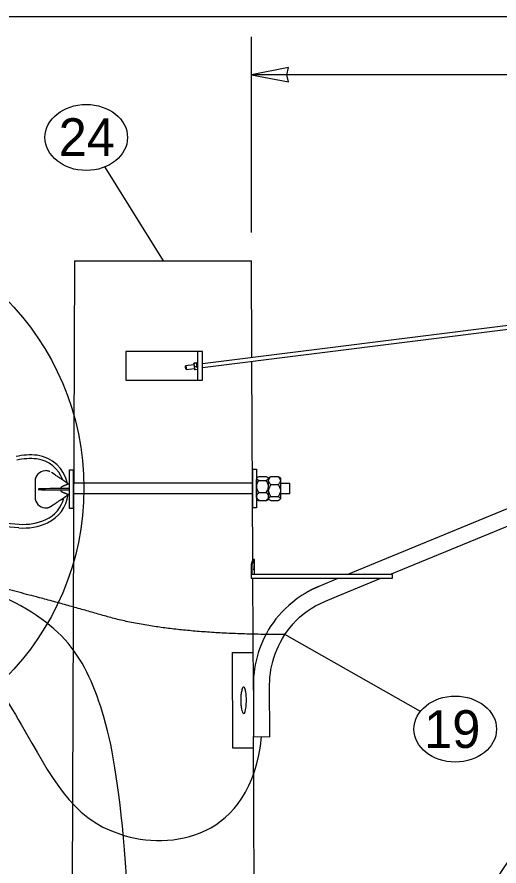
# Model space of a CAD drawing. Extents: x 99862 to 104211, y 98939 to 102076.
# Drawn here: x 100127 to 100331.4, y 101715.8 to 102075.5 of the extents above; entities that cross this region are included whole.
import ezdxf

# ---------------------------------------------------------------- set-up
doc = ezdxf.new("R2010")
doc.units = 0
for name, color, linetype in [('Level 1', 7, 'Continuous'), ('Level 12', 7, 'Continuous'), ('Level 15', 7, 'Continuous'), ('Level 18', 7, 'Continuous'), ('Level 20', 7, 'Continuous'), ('Level 32', 7, 'Continuous'), ('Level 33', 7, 'Continuous'), ('Level 34', 7, 'Continuous'), ('Level 38', 7, 'Continuous'), ('Level 40', 7, 'Continuous'), ('Level 49', 7, 'Continuous'), ('Level 7', 7, 'Continuous')]:
    doc.layers.add(name, color=color, linetype=linetype)

msp = doc.modelspace()

# ---------------------------------------------------------------- linework, layer by layer
at = {"layer": 'Level 1'}
for p, q in [((100151.45, 101972.17), (100149.21, 101433.5)), ((100151.45, 101972.17), (100226.45, 101972.17)), ((100226.62, 101931.09), (100226.45, 101972.17)), ((100226.98, 101845.43), (100226.63, 101929.52)), ((100227.23, 101790.32), (100227.01, 101837.68)), ((100228.7, 101433.5), (100227.29, 101770.61))]:
    msp.add_line(p, q, dxfattribs=at)
msp.add_lwpolyline([(99862, 99999.5), (103151, 99999.5), (103151, 102075.5), (99862, 102075.5)], close=True, dxfattribs=at)
at = {"layer": 'Level 12'}
for points, degree in [([(100176.93, 101638.26), (100173.89, 101734.54), (100164.15, 101799.98), (100138.47, 101825.12), (100098.36, 101838.8)], 3), ([(100240.57, 101813.83), (100191.29, 101813.83), (100136.84, 101829.72), (100099.22, 101838.98)], 2), ([(100072.35, 101826.16), (100099.14, 101823.34), (100133.1, 101771.89), (100157.98, 101718.14), (100226.04, 101726.6), (100230.75, 101770.54)], 3)]:
    msp.add_open_spline(points, degree=degree, dxfattribs=at)
at = {"layer": 'Level 15'}
for p, q in [((100226.45, 101984.17), (100226.45, 102067.04)), ((100473.47, 102051.04), (100226.45, 102051.04)), ((100164.2, 102011.93), (100188.95, 101972.17)), ((100078.2, 101864.74), (100127.92, 101860.61)), ((100127.79, 101859.05), (100078.07, 101863.19)), ((100298.04, 101781.29), (100240.57, 101813.83))]:
    msp.add_line(p, q, dxfattribs=at)
msp.add_lwpolyline([(100226.45, 102051.04), (100242.18, 102047.96), (100241.45, 102051.04), (100242.18, 102054.13)], close=True, dxfattribs=at)
for centre, radius in [((100041.37, 101875.87), 113.99), ((100504.52, 101599.96), 206.11)]:
    msp.add_circle(centre, radius, dxfattribs=at)
for centre, radius, start, end in [((100132.58, 101865.55), 24.41, 83.055, 104.0887), ((100133.71, 101874.86), 15.04, 11.5094, 83.055), ((100132.58, 101865.55), 22.85, 83.055, 104.0887), ((100133.71, 101874.86), 13.48, 19.3591, 83.055), ((100133.71, 101874.86), 13.48, 294.5861, 346.7651), ((100133.71, 101874.86), 15.04, 294.5861, 353.4239), ((100129.81, 101883.38), 24.41, 265.2438, 294.5861), ((100129.81, 101883.38), 22.85, 265.2438, 294.5861)]:
    msp.add_arc(centre, radius, start, end, dxfattribs=at)
at = {"layer": 'Level 18'}
for p, q in [((100238.71, 101877.94), (100242.66, 101877.94)), ((100242.66, 101873.48), (100242.66, 101877.94)), ((100242.66, 101873.48), (100238.71, 101873.48))]:
    msp.add_line(p, q, dxfattribs=at)
at = {"layer": 'Level 20'}
for centre in [(100156.39, 102024.46), (100312.82, 101773.79)]:
    msp.add_ellipse(centre, major_axis=(-17.5, 0), ratio=0.8, dxfattribs=at)
at = {"layer": 'Level 32'}
for p, q in [((100266.99, 101839.23), (100578.4, 101967.79)), ((100285.11, 101839.23), (100583.62, 101962.46)), ((100255.13, 101834.34), (100263.2, 101837.67)), ((100261.55, 101829.51), (100281.33, 101837.67)), ((100257.77, 101827.95), (100261.55, 101829.51)), ((100227.23, 101792.5), (100227.24, 101787.89)), ((100234.21, 101770.48), (100234.14, 101792.52)), ((100227.29, 101770.61), (100234.21, 101770.48))]:
    msp.add_line(p, q, dxfattribs=at)
for points, degree in [([(100247.91, 101830.55), (100250.2, 101832.03), (100252.62, 101833.3), (100255.13, 101834.34)], 2), ([(100247.91, 101830.55), (100242.1, 101826.49), (100235.01, 101819.39), (100228.59, 101806.26), (100227.21, 101797.05), (100227.23, 101792.5)], 3), ([(100234.14, 101792.52), (100234.13, 101796.93), (100235.63, 101805.62), (100243.1, 101818.94), (100251.89, 101825.52), (100257.77, 101827.95)], 3), ([(100227.24, 101787.93), (100227.24, 101787.38), (100227.24, 101786.84), (100227.25, 101786.29), (100227.25, 101784), (100227.26, 101781.71), (100227.29, 101770.61)], 3)]:
    msp.add_open_spline(points, degree=degree, dxfattribs=at)
at = {"layer": 'Level 33'}
for p, q in [((100227.71, 101845.6), (100227.02, 101845.6)), ((100227.72, 101839.23), (100227.72, 101845.58)), ((100226.79, 101839.23), (100226.79, 101843.54)), ((100276.86, 101839.23), (100226.79, 101839.23)), ((100286.23, 101839.23), (100276.97, 101839.23)), ((100277.12, 101839.23), (100277.23, 101839.23)), ((100286.23, 101837.67), (100286.23, 101839.23)), ((100226.32, 101837.67), (100276.86, 101837.67)), ((100276.97, 101837.67), (100286.23, 101837.67)), ((100277.12, 101837.67), (100277.23, 101837.67))]:
    msp.add_line(p, q, dxfattribs=at)
msp.add_ellipse((99942.52, 101829.47), major_axis=(-581.56, 0), ratio=0.027734, start_param=4.201666, end_param=4.202627, dxfattribs=at)
for points, degree in [([(100226.98, 101845.57), (100227, 101845.59), (100227.01, 101845.6), (100227.04, 101845.6), (100227.03, 101845.55), (100226.96, 101845.37), (100226.9, 101845.24), (100226.76, 101844.95), (100226.7, 101844.81), (100226.63, 101844.66)], 3), ([(100226.79, 101843.54), (100227.1, 101844.2), (100227.35, 101844.72), (100227.59, 101845.24), (100227.65, 101845.37), (100227.72, 101845.55), (100227.73, 101845.6), (100227.71, 101845.6)], 3), ([(100226.63, 101844.66), (100226.53, 101844.36), (100226.42, 101843.99), (100226.3, 101843.55)], 2), ([(100226.3, 101843.55), (100226.31, 101841.59), (100226.31, 101839.63), (100226.32, 101837.67)], 2), ([(100227.57, 101841.81), (100227.57, 101841.79), (100227.58, 101841.76), (100227.58, 101841.72), (100227.58, 101841.69), (100227.58, 101841.65), (100227.58, 101841.61), (100227.59, 101841.57), (100227.59, 101841.52), (100227.59, 101841.48), (100227.59, 101841.43), (100227.59, 101841.39), (100227.58, 101841.35), (100227.58, 101841.3), (100227.58, 101841.27), (100227.58, 101841.23), (100227.58, 101841.2), (100227.57, 101841.17), (100227.57, 101841.14), (100227.56, 101841.12), (100227.56, 101841.1), (100227.55, 101841.09), (100227.55, 101841.08), (100227.55, 101841.08), (100227.54, 101841.08), (100227.54, 101841.09), (100227.53, 101841.1), (100227.53, 101841.12), (100227.52, 101841.14), (100227.52, 101841.17), (100227.51, 101841.2), (100227.51, 101841.23), (100227.51, 101841.27), (100227.5, 101841.31), (100227.5, 101841.35), (100227.5, 101841.39), (100227.5, 101841.44), (100227.5, 101841.48), (100227.5, 101841.52), (100227.5, 101841.57), (100227.5, 101841.61), (100227.5, 101841.65), (100227.51, 101841.69), (100227.51, 101841.73), (100227.51, 101841.76), (100227.52, 101841.79), (100227.52, 101841.8), (100227.52, 101841.8), (100227.52, 101841.81)], 3), ([(100227.52, 101843.02), (100227.52, 101843.04), (100227.52, 101843.07), (100227.52, 101843.09), (100227.52, 101843.11), (100227.52, 101843.13), (100227.53, 101843.15), (100227.53, 101843.17), (100227.53, 101843.18), (100227.53, 101843.2), (100227.53, 101843.21), (100227.54, 101843.22), (100227.54, 101843.22), (100227.54, 101843.23), (100227.55, 101843.23), (100227.55, 101843.23), (100227.55, 101843.23), (100227.55, 101843.22), (100227.56, 101843.21), (100227.56, 101843.2), (100227.56, 101843.18), (100227.56, 101843.17), (100227.56, 101843.15), (100227.56, 101843.13), (100227.57, 101843.11), (100227.57, 101843.09), (100227.57, 101843.06), (100227.57, 101843.04), (100227.57, 101843.03), (100227.57, 101843.03), (100227.57, 101843.02)], 3), ([(100227.52, 101841.81), (100227.52, 101841.91), (100227.52, 101842.01), (100227.52, 101842.11), (100227.52, 101842.42), (100227.52, 101842.72), (100227.52, 101843.02)], 3), ([(100227.57, 101843.02), (100227.57, 101842.72), (100227.57, 101842.42), (100227.57, 101842.11), (100227.57, 101842.01), (100227.57, 101841.91), (100227.57, 101841.81)], 3)]:
    msp.add_open_spline(points, degree=degree, dxfattribs=at)
at = {"layer": 'Level 34'}
for p, q in [((100203.62, 101933.77), (100173.1, 101933.77)), ((100173.1, 101933.77), (100173.1, 101921.56)), ((100203.62, 101933.77), (100203.62, 101921.56)), ((100205.65, 101933.77), (100203.62, 101933.77)), ((100205.65, 101921.56), (100205.65, 101933.77)), ((100173.1, 101921.56), (100203.62, 101921.56)), ((100203.62, 101921.56), (100205.65, 101921.56))]:
    msp.add_line(p, q, dxfattribs=at)
at = {"layer": 'Level 38'}
for p, q in [((100134.71, 101878.79), (100134.7, 101872.04)), ((100226.91, 101877.94), (100150.88, 101877.94)), ((100242.66, 101877.94), (100242.66, 101877.94)), ((100146.94, 101875.67), (100141.08, 101875.68)), ((100141.08, 101875.14), (100146.94, 101875.15)), ((100149.27, 101875.7), (100147.8, 101875.7)), ((100147.8, 101875.13), (100149.27, 101875.13)), ((100148.81, 101877.56), (100148.81, 101877.56)), ((100148.81, 101873.26), (100148.81, 101873.26)), ((100226.91, 101873.48), (100150.88, 101873.48))]:
    msp.add_line(p, q, dxfattribs=at)
for centre, start, end in [((100139.21, 101878.79), 94.053, 179.9934), ((100139.2, 101872.04), 179.9934, 265.9339)]:
    msp.add_arc(centre, 4.5, start, end, dxfattribs=at)
for centre, start_param, end_param in [((100143.01, 101875.46), 4.989541, 6.265171), ((100143.01, 101875.36), 0.018014, 1.293644)]:
    msp.add_ellipse(centre, major_axis=(-7.03, 0), ratio=0.031999, start_param=start_param, end_param=end_param, dxfattribs=at)
for points, degree in [([(100141.01, 101882.85), (100140.68, 101883.01), (100140.32, 101883.13), (100139.61, 101883.28), (100139.25, 101883.3), (100138.89, 101883.28)], 3), ([(100146.74, 101879.11), (100146.12, 101879.53), (100145.49, 101879.94), (100144.87, 101880.35), (100143.78, 101881.07), (100142.7, 101881.79), (100141.61, 101882.5)], 3), ([(100148.81, 101877.56), (100148.15, 101878.11), (100147.46, 101878.64), (100146.74, 101879.11)], 2), ([(100146.3, 101876.57), (100146.12, 101876.49), (100145.96, 101876.4), (100145.75, 101876.28), (100145.69, 101876.24), (100145.62, 101876.15), (100145.61, 101876.12), (100145.63, 101876.1)], 3), ([(100145.63, 101874.73), (100145.61, 101874.71), (100145.62, 101874.67), (100145.69, 101874.59), (100145.76, 101874.55), (100145.96, 101874.42), (100146.12, 101874.34), (100146.3, 101874.26)], 3), ([(100147.93, 101877.27), (100147.4, 101877.03), (100146.83, 101876.81), (100146.3, 101876.57)], 2), ([(100146.3, 101874.26), (100146.83, 101874.01), (100147.4, 101873.79), (100147.93, 101873.56)], 2), ([(100147.8, 101875.7), (100147.65, 101875.7), (100147.51, 101875.69), (100147.37, 101875.69), (100147.24, 101875.69), (100147.11, 101875.68), (100146.98, 101875.67), (100146.97, 101875.67), (100146.96, 101875.67), (100146.94, 101875.67)], 3), ([(100146.94, 101875.15), (100146.96, 101875.15), (100146.97, 101875.15), (100146.98, 101875.15), (100147.13, 101875.14), (100147.27, 101875.14), (100147.41, 101875.13), (100147.54, 101875.13), (100147.67, 101875.13), (100147.8, 101875.13)], 3), ([(100148.81, 101877.56), (100148.53, 101877.49), (100148.22, 101877.4), (100147.93, 101877.27)], 2), ([(100149.27, 101877.58), (100149.12, 101877.57), (100148.96, 101877.57), (100148.81, 101877.56)], 2), ([(100141.61, 101868.32), (100142.24, 101868.73), (100142.86, 101869.15), (100143.49, 101869.56), (100144.55, 101870.26), (100145.61, 101870.96), (100146.67, 101871.66), (100146.69, 101871.68), (100146.72, 101871.69), (100146.74, 101871.71)], 3), ([(100146.74, 101871.71), (100147.46, 101872.19), (100148.14, 101872.71), (100148.81, 101873.26)], 2), ([(100147.93, 101873.56), (100148.22, 101873.43), (100148.53, 101873.33), (100148.81, 101873.26)], 2), ([(100148.81, 101873.26), (100148.96, 101873.26), (100149.12, 101873.25), (100149.27, 101873.25)], 2), ([(100138.89, 101867.55), (100139.61, 101867.5), (100140.34, 101867.65), (100141, 101867.98)], 2), ([(100141, 101867.98), (100141.21, 101868.08), (100141.41, 101868.19), (100141.61, 101868.32)], 2)]:
    msp.add_open_spline(points, degree=degree, dxfattribs=at)
at = {"layer": 'Level 40'}
for p, q in [((100228.6, 101876.87), (100228.6, 101879.51)), ((100229.63, 101880.79), (100232.62, 101880.79)), ((100229.63, 101879.15), (100232.62, 101879.15)), ((100233.3, 101880.44), (100233.3, 101880.44)), ((100233.65, 101879.88), (100233.65, 101880.05)), ((100233.65, 101876.87), (100233.65, 101879.88)), ((100233.65, 101876.87), (100233.65, 101879.51)), ((100234.01, 101880.44), (100233.74, 101880.26)), ((100234.68, 101880.79), (100237.68, 101880.79)), ((100238.71, 101880.21), (100238.35, 101880.45)), ((100238.71, 101880.21), (100238.71, 101879.25)), ((100238.71, 101879.25), (100238.71, 101878.89)), ((100238.71, 101878.89), (100238.71, 101875.07)), ((100228.6, 101876.35), (100228.6, 101876.87)), ((100228.6, 101871.91), (100228.6, 101876.35)), ((100229.63, 101874.07), (100232.62, 101874.07)), ((100233.65, 101876.35), (100233.65, 101876.87)), ((100233.65, 101876.35), (100233.65, 101876.87)), ((100233.65, 101872.52), (100233.65, 101876.35)), ((100233.65, 101872.52), (100233.65, 101876.35)), ((100234.68, 101877.35), (100237.68, 101877.35)), ((100238.71, 101875.07), (100238.71, 101874.55)), ((100238.71, 101874.55), (100238.71, 101871.53)), ((100228.6, 101872.17), (100228.6, 101872.52)), ((100228.95, 101870.97), (100228.68, 101871.15)), ((100229.63, 101870.63), (100232.62, 101870.63)), ((100233.65, 101871.21), (100233.3, 101870.97)), ((100233.65, 101872.17), (100233.65, 101872.52)), ((100233.65, 101872.17), (100233.65, 101872.52)), ((100233.65, 101871.21), (100233.65, 101872.17)), ((100233.65, 101871.91), (100233.65, 101872.17)), ((100234.68, 101872.27), (100237.68, 101872.27)), ((100234.68, 101870.63), (100237.68, 101870.63)), ((100238.35, 101870.97), (100238.35, 101870.97)), ((100238.71, 101871.53), (100238.71, 101871.36))]:
    msp.add_line(p, q, dxfattribs=at)
for points in [[(100149.26, 101883.57), (100150.88, 101883.57), (100150.88, 101867.21), (100149.26, 101867.21)], [(100226.97, 101883.89), (100228.59, 101883.89), (100228.59, 101867.53), (100226.97, 101867.53)]]:
    msp.add_lwpolyline(points, close=True, dxfattribs=at)
for points, degree in [([(100228.63, 101879.81), (100228.62, 101879.72), (100228.61, 101879.62), (100228.6, 101879.51)], 2), ([(100228.6, 101876.87), (100228.64, 101877.29), (100228.77, 101877.7), (100229.14, 101878.46), (100229.38, 101878.81), (100229.63, 101879.15)], 3), ([(100228.63, 101879.81), (100228.65, 101879.94), (100228.67, 101880.07), (100228.67, 101880.2)], 3), ([(100229.63, 101879.15), (100229.37, 101879.26), (100229.14, 101879.37), (100228.81, 101879.59), (100228.69, 101879.7), (100228.63, 101879.81)], 3), ([(100228.67, 101880.2), (100228.74, 101880.28), (100228.83, 101880.36), (100229.14, 101880.57), (100229.37, 101880.68), (100229.63, 101880.79)], 3), ([(100232.62, 101880.79), (100232.88, 101880.68), (100233.12, 101880.57), (100233.48, 101880.32), (100233.62, 101880.19), (100233.65, 101880.05)], 3), ([(100233.65, 101879.88), (100233.62, 101879.75), (100233.49, 101879.62), (100233.12, 101879.37), (100232.88, 101879.26), (100232.62, 101879.15)], 3), ([(100233.65, 101876.87), (100233.62, 101877.29), (100233.48, 101877.7), (100233.12, 101878.46), (100232.88, 101878.81), (100232.62, 101879.15)], 3), ([(100234.68, 101880.79), (100234.43, 101880.56), (100234.19, 101880.32), (100233.82, 101879.81), (100233.69, 101879.53), (100233.65, 101879.25)], 3), ([(100233.65, 101879.51), (100233.68, 101879.73), (100233.7, 101879.91), (100233.71, 101880.04), (100233.73, 101880.19), (100233.74, 101880.26), (100233.74, 101880.26)], 3), ([(100233.65, 101878.89), (100233.69, 101878.61), (100233.82, 101878.34), (100234.19, 101877.82), (100234.43, 101877.58), (100234.68, 101877.35)], 3), ([(100234.01, 101880.44), (100234.19, 101880.57), (100234.43, 101880.68), (100234.68, 101880.79)], 2), ([(100237.68, 101880.79), (100237.94, 101880.68), (100238.17, 101880.57), (100238.35, 101880.44)], 2), ([(100238.71, 101879.25), (100238.67, 101879.53), (100238.54, 101879.81), (100238.17, 101880.32), (100237.94, 101880.56), (100237.68, 101880.79)], 3), ([(100237.68, 101877.35), (100237.94, 101877.58), (100238.17, 101877.82), (100238.54, 101878.33), (100238.67, 101878.61), (100238.71, 101878.89)], 3), ([(100229.63, 101874.07), (100229.37, 101874.4), (100229.14, 101874.76), (100228.77, 101875.52), (100228.64, 101875.92), (100228.6, 101876.35)], 3), ([(100228.6, 101872.52), (100228.64, 101872.81), (100228.77, 101873.08), (100229.14, 101873.6), (100229.37, 101873.84), (100229.63, 101874.07)], 3), ([(100232.62, 101874.07), (100232.88, 101874.4), (100233.12, 101874.76), (100233.48, 101875.52), (100233.62, 101875.92), (100233.65, 101876.35)], 3), ([(100232.62, 101874.07), (100232.88, 101873.84), (100233.12, 101873.6), (100233.48, 101873.08), (100233.62, 101872.81), (100233.65, 101872.52)], 3), ([(100234.68, 101877.35), (100234.43, 101877.02), (100234.19, 101876.66), (100233.82, 101875.9), (100233.69, 101875.49), (100233.65, 101875.07)], 3), ([(100233.65, 101874.55), (100233.69, 101874.13), (100233.82, 101873.72), (100234.19, 101872.96), (100234.43, 101872.6), (100234.68, 101872.27)], 3), ([(100237.68, 101877.35), (100237.93, 101877.02), (100238.17, 101876.66), (100238.54, 101875.9), (100238.67, 101875.49), (100238.71, 101875.07)], 3), ([(100238.71, 101874.55), (100238.67, 101874.13), (100238.54, 101873.72), (100238.17, 101872.96), (100237.93, 101872.6), (100237.68, 101872.27)], 3), ([(100229.63, 101870.63), (100229.37, 101870.85), (100229.14, 101871.09), (100228.77, 101871.61), (100228.64, 101871.88), (100228.6, 101872.17)], 3), ([(100228.6, 101871.91), (100228.62, 101871.68), (100228.64, 101871.51), (100228.66, 101871.38), (100228.67, 101871.23), (100228.68, 101871.15), (100228.68, 101871.15)], 3), ([(100228.95, 101870.97), (100229.14, 101870.85), (100229.37, 101870.74), (100229.63, 101870.63)], 2), ([(100233.65, 101872.17), (100233.62, 101871.88), (100233.49, 101871.61), (100233.12, 101871.09), (100232.88, 101870.85), (100232.62, 101870.63)], 3), ([(100232.62, 101870.63), (100232.88, 101870.74), (100233.12, 101870.85), (100233.3, 101870.97)], 2), ([(100234.68, 101872.27), (100234.43, 101872.16), (100234.19, 101872.05), (100233.86, 101871.82), (100233.74, 101871.72), (100233.68, 101871.61)], 3), ([(100233.68, 101871.61), (100233.71, 101871.48), (100233.72, 101871.35), (100233.73, 101871.22)], 3), ([(100233.73, 101871.22), (100233.79, 101871.13), (100233.89, 101871.05), (100234.19, 101870.85), (100234.43, 101870.74), (100234.68, 101870.63)], 3), ([(100238.71, 101871.53), (100238.67, 101871.67), (100238.54, 101871.8), (100238.17, 101872.04), (100237.94, 101872.16), (100237.68, 101872.27)], 3), ([(100237.68, 101870.63), (100237.94, 101870.74), (100238.17, 101870.85), (100238.54, 101871.09), (100238.67, 101871.23), (100238.71, 101871.36)], 3)]:
    msp.add_open_spline(points, degree=degree, dxfattribs=at)
at = {"layer": 'Level 49'}
for p, q in [((100581.75, 101975.69), (100205.65, 101928.5)), ((100205.65, 101926.93), (100582.37, 101974.2)), ((100202.03, 101928.17), (100198.52, 101927.73)), ((100203.6, 101928.37), (100203.29, 101928.33)), ((100198.71, 101926.18), (100202.22, 101926.62)), ((100203.48, 101926.78), (100203.61, 101926.79)), ((100218.48, 101765.71), (100218.32, 101806.29)), ((100218.32, 101806.29), (100227.19, 101806.29)), ((100227.31, 101765.71), (100218.48, 101765.71))]:
    msp.add_line(p, q, dxfattribs=at)
msp.add_ellipse((100198.61, 101926.96), major_axis=(0.097, -0.775), ratio=0.101579, dxfattribs=at)
for points, degree in [([(100203.48, 101926.78), (100203.48, 101926.78), (100203.44, 101927.09), (100203.38, 101927.54), (100203.32, 101928), (100203.29, 101928.32), (100203.29, 101928.33)], 4), ([(100223.96, 101781.9), (100223.75, 101780.9), (100223.46, 101780.37), (100222.83, 101780.46), (100222.5, 101781.1), (100222.01, 101783.2), (100221.85, 101784.68), (100221.86, 101787.65), (100222.03, 101789.09), (100222.53, 101791.08), (100222.86, 101791.62), (100223.48, 101791.55), (100223.77, 101790.92), (100224.17, 101788.8), (100224.28, 101787.31), (100224.28, 101784.35), (100224.17, 101782.91), (100223.96, 101781.9)], 3)]:
    msp.add_open_spline(points, degree=degree, dxfattribs=at)
at = {"layer": 'Level 7'}
for p, q in [((100201.97, 101928.74), (100201.99, 101928.77)), ((100202.16, 101928.78), (100203.21, 101928.91)), ((100203.22, 101928.93), (100202.18, 101928.8)), ((100203.22, 101928.93), (100203.21, 101928.91)), ((100203.21, 101928.91), (100203.38, 101927.53)), ((100203.3, 101928.33), (100203.22, 101928.93)), ((100202.32, 101926.04), (100202.3, 101926.06)), ((100202.33, 101927.4), (100203.38, 101927.53)), ((100203.55, 101926.18), (100202.5, 101926.05)), ((100203.38, 101927.53), (100203.55, 101926.18)), ((100203.49, 101926.78), (100203.56, 101926.2)), ((100203.56, 101926.2), (100203.55, 101926.18))]:
    msp.add_line(p, q, dxfattribs=at)
msp.add_ellipse((100202.13, 101927.4), major_axis=(-0.17, 1.34), ratio=0.008672, start_param=0.009974, end_param=3.131717, dxfattribs=at)
for points, degree in [([(100202.18, 101928.8), (100202.07, 101928.78), (100201.99, 101928.77), (100201.98, 101928.76), (100202.06, 101928.77), (100202.16, 101928.78)], 3), ([(100202.16, 101928.78), (100202.12, 101928.66), (100202.09, 101928.54), (100202.05, 101928.31), (100202.05, 101928.19), (100202.09, 101927.83), (100202.19, 101927.61), (100202.33, 101927.4)], 3), ([(100202.33, 101927.4), (100202.29, 101927.29), (100202.26, 101927.17), (100202.22, 101926.94), (100202.22, 101926.82), (100202.26, 101926.47), (100202.37, 101926.25), (100202.5, 101926.05)], 3), ([(100202.5, 101926.05), (100202.4, 101926.04), (100202.33, 101926.03), (100202.32, 101926.04)], 2)]:
    msp.add_open_spline(points, degree=degree, dxfattribs=at)

# ---------------------------------------------------------------- texts
at = {"layer": 'Level 20'}
for s, p in [('24', (100144.69, 102016.59)), ('19', (100299.66, 101765.79))]:
    msp.add_text(s, height=16, dxfattribs=at).set_placement(p)

doc.saveas('drawing.dxf')
